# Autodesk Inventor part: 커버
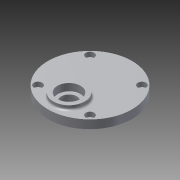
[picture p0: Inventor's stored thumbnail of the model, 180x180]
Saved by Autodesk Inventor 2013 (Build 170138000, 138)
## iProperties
Created: 2015-07
Part Number: 커버
Material: 알루미늄 6061
Document SubType Name: Modeling
Designer: user
Density: 1 g/cm^3
Author: user
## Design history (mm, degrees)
sketch "스케치1"
  geometry: C1 r 40 at (0, 0); 1 further point
  constraints: 1 centre point, 1 coincident
  dimensions: "d1" = 80 diameter of C1
extrude "돌출1" new body sketch "스케치1" distance "d2" = 9; taper "d3" = 0 deg
sketch "스케치2"
  geometry: L1 (0, 0)-(0, -20); C1 r 40 at (0, 0) reference; C2 r 15 at (0, -20)
  constraints: 2 end point, 1 centre point, 1 coincident, 1 vertical
  dimensions: "d5" = 20 distance of L1.start L1.end; "d6" = 30 diameter of C2
extrude "돌출2" join sketch "스케치2" distance "d7" = 4; taper "d8" = 0 deg
sketch "스케치3"
  geometry: C1 r 15 at (0, 0) reference; C2 r 11 at (0, 0); 1 further point
  constraints: 1 centre point, 1 coincident
  dimensions: "d9" = 22 diameter of C2
extrude "돌출3" cut sketch "스케치3" distance "d10" = 7; taper "d11" = 0 deg
sketch "스케치4"
  geometry: L1 (0, 0)-(0, -20); L2 (0, 0)-(0, 11); C1 r 40 at (0, 0) reference; C2 r 14 at (0, 11); C3 r 14 at (0, -20)
  constraints: 4 end point, 2 centre point, 2 coincident, 1 collinear, 1 vertical
  dimensions: "d12" = 20 distance of L1.start L1.end; "d13" = 11 distance of L1.start L2.end; "d14" = 28 diameter of C2; "d15" = 28 diameter of C3
extrude "돌출4" join sketch "스케치4" distance "d16" = 3; taper "d17" = 0 deg
sketch "스케치5"
  geometry: C1 r 14 at (0, 0) reference; C2 r 14 at (0, -31) reference; C3 r 11 at (0, 0); C4 r 11 at (0, -31); 1 further point
  constraints: 2 centre point, 2 coincident
  dimensions: "d18" = 22 diameter of C3; "d19" = 22 diameter of C4
extrude "돌출5" cut sketch "스케치5" distance "d20" = 7; taper "d21" = 0 deg
sketch "스케치6"
  geometry: C1 r 9 at (0, 0); 2 further points
  constraints: 1 centre point, 1 coincident, 1 vertical alignment
  dimensions: "d22" = 18 diameter of C1
extrude "돌출6" cut sketch "스케치6" distance "d23" = 1; taper "d24" = 0 deg
sketch "스케치7"
  geometry: C1 r 11 at (0, 0) reference; C2 r 7.5 at (0, 0); 1 further point
  constraints: 1 centre point, 1 coincident
  dimensions: "d25" = 15 diameter of C2
extrude "돌출7" cut sketch "스케치7" distance "d26" = 2; taper "d27" = 0 deg
fillet "모깎기1" dims "d28" = 2
chamfer "모따기1" distance "d29" = 1; stored, may be unused: second distance "d30" = 2, angle "d31" = 45 deg
fillet "모깎기2" dims "d32" = 2
sketch "스케치8"
  geometry: L1 (0, 0)-(-24.749, 24.749); C1 r 40 at (0, 0) reference
  constraints: 2 end point
  dimensions: "d33" = 35 distance of L1.start L1.end
hole "구멍1" sketch "스케치8" at (-24.749, 24.749) diameter "d35" = 4.5; stored, may be unused: countersink angle "d39" = 90 deg, drill point angle "d41" = 118 deg; dims "d36" = 6, "d37" = 8, "d38" = 4.4, "d40" = 15
fillet "모깎기3" dims "d45" = 0.3
node "솔리드1"
pattern_circular "원형 패턴1" dims angle "d43" = 360 deg
node "절단 모서리 투영1"
